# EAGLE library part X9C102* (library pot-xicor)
Digital POTENTIOMETER
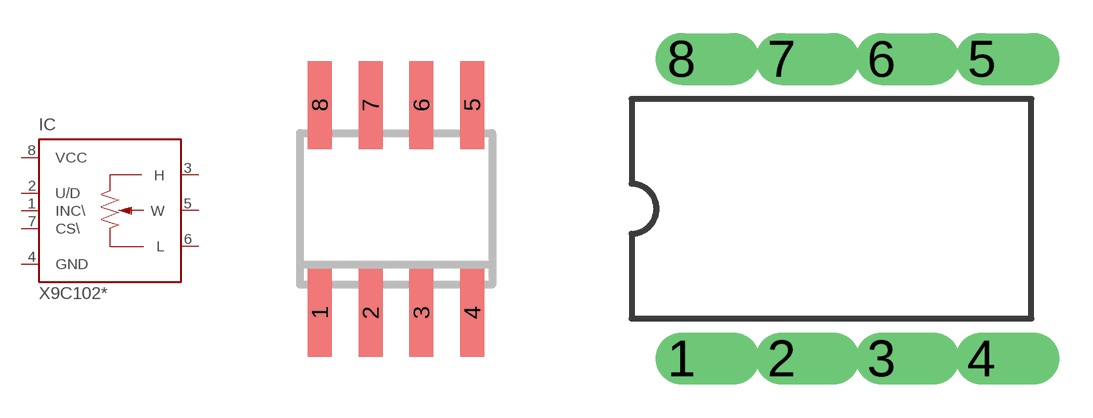
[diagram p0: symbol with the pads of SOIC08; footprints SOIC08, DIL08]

Designator prefix IC

## X9C102S  [SOIC08]
1  INC\  in
2  U/D  in
3  H  pas
4  GND  pwr
5  W  pas
6  L  pas
7  CS\  in
8  VCC  pwr

## X9C102P  [DIL08]
Pads as for SOIC08

## Footprint SOIC08 (pad centres in mm)
Small Outline Package
smd 0.6 x 2.2: 1 -1.905,-2.6; 2 -0.635,-2.6; 3 0.635,-2.6; 4 1.905,-2.6; 5 1.905,2.6; 6 0.635,2.6; 7 -0.635,2.6; 8 -1.905,2.6

## Footprint DIL08 (pad centres in mm)
Dual In Line
drill 0.813 offset: 1 -3.81,-3.81; 2 -1.27,-3.81; 3 1.27,-3.81; 4 3.81,-3.81; 5 3.81,3.81; 6 1.27,3.81; 7 -1.27,3.81; 8 -3.81,3.81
